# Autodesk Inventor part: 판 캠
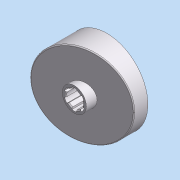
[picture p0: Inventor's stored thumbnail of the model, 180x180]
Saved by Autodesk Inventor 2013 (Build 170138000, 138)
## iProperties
Company: 한국ATC센터
Created: 2012-05
Part Number: 판 캠
Document SubType Name: 모델링
Designer: KYOUNG IL JANG
Mass: 681.586 g
Surface Area: 331.301 cm^2
Volume: 86.8262 cm^3
Density: 7.85 g/cm^3
Material: 강
변환 표준: STEP AP214IS
파일 이름: C:\Users\SeoGD\Desktop\?쒗뿕\??stp
전처리기: Build: 253, Release: 2010 SP1 - Date: Wed 07/29/2009
전송 단위: 밀리미터
불확실성: 0.01
Author: KYOUNG IL JANG
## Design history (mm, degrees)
node "작업 평면4"
sketch "스케치1"
  geometry: C1 r 44.5 at (0, 0); 1 further point
  constraints: 1 centre point, 1 coincident
  dimensions: "d25" = 89 diameter of C1
extrude "돌출1" new body sketch "스케치1" distance "d1" = 40; taper "d2" = 0 deg
sketch "스케치2"
  geometry: L1 (-44.5, 15)-(44.5, 38.847); L2 (-44.5, 0)-(-44.5, 40) reference; L3 (-44.5, 40)-(44.5, 40) reference; L4 (44.5, 0)-(44.5, 40) reference; 1 further point
  constraints: 2 end point, 2 point on line
  dimensions: "d26" = 15 distance of L2.start L1.start; "d27" = 75 deg angle of L1 L2
extrude "돌출2" cut sketch "스케치2" stored distance "d5" = 40; taper "d6" = 0 deg
node "작업 평면1"
sketch "스케치3"
  geometry: C1 r 13 at (0, 0); 1 further point
  constraints: 1 centre point, 1 coincident
  dimensions: "d9" = 26 diameter of C1
extrude "돌출3" join sketch "스케치3" distance "d10" = 38; taper "d11" = 0 deg
hole "구멍1" diameter "d14" = 18; stored, may be unused: countersink angle "d18" = 90 deg, drill point angle "d20" = 118 deg; dims "d12" = 10, "d13" = 10, "d15" = 6, "d16" = 4, "d17" = 2, "d19" = 8
feature "쉘2" dims "d29" = 5
sketch "스케치6"
  geometry: C1 r 17.5 at (0, 0); C2 r 14 at (0, 0) reference; 1 further point
  constraints: 1 centre point, 1 coincident
  dimensions: "d28" = 35 diameter of C1
extrude "돌출4" join sketch "스케치6" stored distance "d30" = 38; taper "d31" = 0 deg
fillet "모깎기1" dims "d32" = 3
chamfer "모따기1" distance "d21" = 1; stored, may be unused: second distance "d22" = 2, angle "d23" = 45 deg
sketch "스케치7"
  geometry: L1 (-12.374, 12.374)-(-27.931, 27.931); A1 r 39.5 centre (0, 0) between (-27.931, 27.931) and (0, 39.5) reference; 2 further points
  constraints: 2 end point, 2 point on circle, 1 point on line, 1 vertical alignment, 2 other
  dimensions: "d33" = 45 deg dimension on point (0, 0) L1.start A1.end
feature "리브1" sketch "스케치7" dims "d34" = 5, "d35" = 1, "d36" = 0
fillet "모깎기2" dims "d37" = 3
sketch "스케치8"
  geometry: L1 (2.5, 10.712)-(2.5, 8.646); L2 (-2.5, 10.712)-(-2.5, 8.646); A1 r 11 centre (0, 0) between (2.5, 10.712) and (-2.5, 10.712); A2 r 9 centre (0, 0) between (2.5, 8.646) and (-2.5, 8.646) reference; 1 further point
  constraints: 4 end point, 4 point on circle, 2 parallel, 1 centre point, 1 coincident, 1 vertical
  dimensions: "d41" = 22 diameter of A1; "d42" = 5 distance between parallel lines of L1 L2
extrude "돌출5" cut sketch "스케치8" stored distance "d43" = 38; taper "d44" = 0 deg
fillet "모깎기3" dims "d48" = 1
node "솔리드1"
node "솔리드 본체"
node "곡면 본체"
pattern_circular "원형 패턴1" dims angle "d39" = 360 deg
pattern_circular "원형 패턴2" dims angle "d46" = 360 deg
node "솔리드2"
